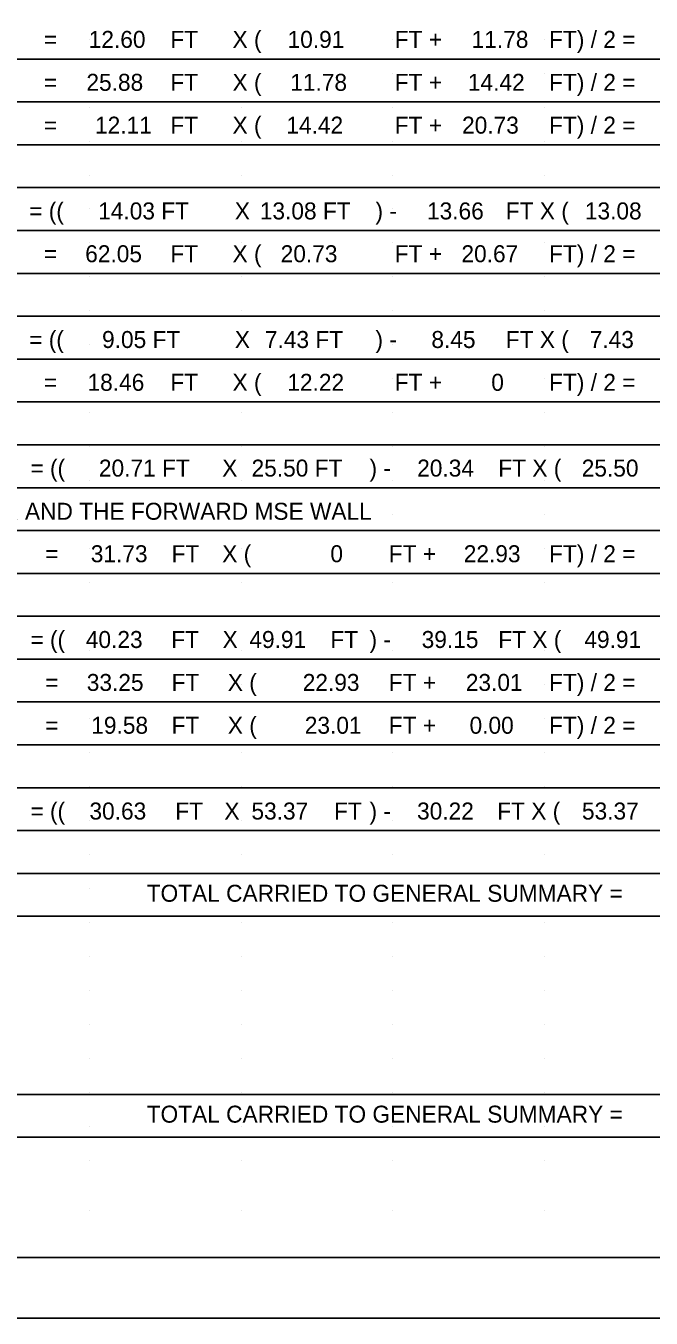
# Model space of a CAD drawing. Extents: x 2073163.5 to 2073197.5, y 634076.4 to 634098.4.
# Drawn here: x 2073186.05 to 2073191.2, y 634076.43 to 634087.09 of the extents above; entities that cross this region are included whole.
import ezdxf

# ---------------------------------------------------------------- set-up
doc = ezdxf.new("R2010")
doc.units = 0
for name, color, linetype in [('SC_Scratch1', 7, 'Continuous'), ('SH_Border', 7, 'Continuous'), ('SH_Cut_Line', 7, 'Continuous'), ('SH_Data', 7, 'Continuous'), ('SH_Text', 7, 'Continuous')]:
    doc.layers.add(name, color=color, linetype=linetype)

msp = doc.modelspace()

# ---------------------------------------------------------------- linework, layer by layer
at = {"layer": 'SC_Scratch1'}
for p, q in [((2073180.369, 634086.814), (2073194.796, 634086.814)), ((2073180.369, 634086.461), (2073194.796, 634086.461)), ((2073180.369, 634086.107), (2073194.796, 634086.107)), ((2073180.369, 634085.754), (2073194.796, 634085.754)), ((2073180.369, 634085.401), (2073194.796, 634085.401)), ((2073180.369, 634085.047), (2073194.796, 634085.047)), ((2073180.369, 634084.694), (2073194.796, 634084.694)), ((2073180.369, 634084.34), (2073194.796, 634084.34)), ((2073180.369, 634083.987), (2073194.796, 634083.987)), ((2073180.369, 634083.634), (2073194.796, 634083.634)), ((2073180.369, 634083.28), (2073194.796, 634083.28)), ((2073180.369, 634082.927), (2073194.796, 634082.927)), ((2073180.369, 634082.574), (2073194.796, 634082.574)), ((2073180.369, 634082.22), (2073194.796, 634082.22)), ((2073180.369, 634081.867), (2073194.796, 634081.867)), ((2073180.369, 634081.514), (2073194.796, 634081.514)), ((2073180.369, 634081.16), (2073194.796, 634081.16)), ((2073180.369, 634080.807), (2073194.796, 634080.807)), ((2073180.369, 634080.454), (2073194.796, 634080.454)), ((2073180.369, 634080.1), (2073194.796, 634080.1)), ((2073180.369, 634079.747), (2073194.796, 634079.747)), ((2073180.369, 634078.279), (2073194.796, 634078.279)), ((2073180.369, 634077.926), (2073194.796, 634077.926))]:
    msp.add_line(p, q, dxfattribs=at)
at = {"layer": 'SH_Border'}
msp.add_lwpolyline([(2073165.007, 634097.934), (2073197.007, 634097.934), (2073197.007, 634076.934), (2073165.007, 634076.934)], close=True, dxfattribs=at)
at = {"layer": 'SH_Cut_Line'}
msp.add_lwpolyline([(2073163.507, 634076.434), (2073197.507, 634076.434), (2073197.507, 634098.434), (2073163.507, 634098.434)], close=True, dxfattribs=at)
at = {"layer": 'SH_Data'}
for p, q in [((2073186.571, 634086.978), (2073186.571, 634086.978)), ((2073187.821, 634086.978), (2073187.821, 634086.978)), ((2073189.071, 634086.978), (2073189.071, 634086.978)), ((2073190.321, 634086.978), (2073190.321, 634086.978)), ((2073186.571, 634086.698), (2073186.571, 634086.698)), ((2073187.821, 634086.698), (2073187.821, 634086.698)), ((2073189.071, 634086.698), (2073189.071, 634086.698)), ((2073190.321, 634086.698), (2073190.321, 634086.698)), ((2073186.571, 634086.418), (2073186.571, 634086.418)), ((2073187.821, 634086.418), (2073187.821, 634086.418)), ((2073189.071, 634086.418), (2073189.071, 634086.418)), ((2073190.321, 634086.418), (2073190.321, 634086.418)), ((2073186.571, 634086.138), (2073186.571, 634086.138)), ((2073187.821, 634086.138), (2073187.821, 634086.138)), ((2073189.071, 634086.138), (2073189.071, 634086.138)), ((2073190.321, 634086.138), (2073190.321, 634086.138)), ((2073186.571, 634085.858), (2073186.571, 634085.858)), ((2073187.821, 634085.858), (2073187.821, 634085.858)), ((2073189.071, 634085.858), (2073189.071, 634085.858)), ((2073190.321, 634085.858), (2073190.321, 634085.858)), ((2073186.571, 634085.578), (2073186.571, 634085.578)), ((2073187.821, 634085.578), (2073187.821, 634085.578)), ((2073189.071, 634085.578), (2073189.071, 634085.578)), ((2073190.321, 634085.578), (2073190.321, 634085.578)), ((2073186.571, 634085.298), (2073186.571, 634085.298)), ((2073187.821, 634085.298), (2073187.821, 634085.298)), ((2073189.071, 634085.298), (2073189.071, 634085.298)), ((2073190.321, 634085.298), (2073190.321, 634085.298)), ((2073186.571, 634085.018), (2073186.571, 634085.018)), ((2073187.821, 634085.018), (2073187.821, 634085.018)), ((2073189.071, 634085.018), (2073189.071, 634085.018)), ((2073190.321, 634085.018), (2073190.321, 634085.018)), ((2073186.571, 634084.738), (2073186.571, 634084.738)), ((2073187.821, 634084.738), (2073187.821, 634084.738)), ((2073189.071, 634084.738), (2073189.071, 634084.738)), ((2073190.321, 634084.738), (2073190.321, 634084.738)), ((2073186.571, 634084.458), (2073186.571, 634084.458)), ((2073187.821, 634084.458), (2073187.821, 634084.458)), ((2073189.071, 634084.458), (2073189.071, 634084.458)), ((2073190.321, 634084.458), (2073190.321, 634084.458)), ((2073186.571, 634084.178), (2073186.571, 634084.178)), ((2073187.821, 634084.178), (2073187.821, 634084.178)), ((2073189.071, 634084.178), (2073189.071, 634084.178)), ((2073190.321, 634084.178), (2073190.321, 634084.178)), ((2073186.571, 634083.898), (2073186.571, 634083.898)), ((2073187.821, 634083.898), (2073187.821, 634083.898)), ((2073189.071, 634083.898), (2073189.071, 634083.898)), ((2073190.321, 634083.898), (2073190.321, 634083.898)), ((2073186.571, 634083.618), (2073186.571, 634083.618)), ((2073187.821, 634083.618), (2073187.821, 634083.618)), ((2073189.071, 634083.618), (2073189.071, 634083.618)), ((2073190.321, 634083.618), (2073190.321, 634083.618)), ((2073186.571, 634083.338), (2073186.571, 634083.338)), ((2073187.821, 634083.338), (2073187.821, 634083.338)), ((2073189.071, 634083.338), (2073189.071, 634083.338)), ((2073190.321, 634083.338), (2073190.321, 634083.338)), ((2073186.571, 634083.058), (2073186.571, 634083.058)), ((2073187.821, 634083.058), (2073187.821, 634083.058)), ((2073189.071, 634083.058), (2073189.071, 634083.058)), ((2073190.321, 634083.058), (2073190.321, 634083.058)), ((2073186.571, 634082.778), (2073186.571, 634082.778)), ((2073187.821, 634082.778), (2073187.821, 634082.778)), ((2073189.071, 634082.778), (2073189.071, 634082.778)), ((2073190.321, 634082.778), (2073190.321, 634082.778)), ((2073186.571, 634082.498), (2073186.571, 634082.498)), ((2073187.821, 634082.498), (2073187.821, 634082.498)), ((2073189.071, 634082.498), (2073189.071, 634082.498)), ((2073190.321, 634082.498), (2073190.321, 634082.498)), ((2073186.571, 634082.218), (2073186.571, 634082.218)), ((2073187.821, 634082.218), (2073187.821, 634082.218)), ((2073189.071, 634082.218), (2073189.071, 634082.218)), ((2073190.321, 634082.218), (2073190.321, 634082.218)), ((2073186.571, 634081.938), (2073186.571, 634081.938)), ((2073187.821, 634081.938), (2073187.821, 634081.938)), ((2073189.071, 634081.938), (2073189.071, 634081.938)), ((2073190.321, 634081.938), (2073190.321, 634081.938)), ((2073186.571, 634081.658), (2073186.571, 634081.658)), ((2073187.821, 634081.658), (2073187.821, 634081.658)), ((2073189.071, 634081.658), (2073189.071, 634081.658)), ((2073190.321, 634081.658), (2073190.321, 634081.658)), ((2073186.571, 634081.378), (2073186.571, 634081.378)), ((2073187.821, 634081.378), (2073187.821, 634081.378)), ((2073189.071, 634081.378), (2073189.071, 634081.378)), ((2073190.321, 634081.378), (2073190.321, 634081.378)), ((2073186.571, 634081.098), (2073186.571, 634081.098)), ((2073187.821, 634081.098), (2073187.821, 634081.098)), ((2073189.071, 634081.098), (2073189.071, 634081.098)), ((2073190.321, 634081.098), (2073190.321, 634081.098)), ((2073186.571, 634080.818), (2073186.571, 634080.818)), ((2073187.821, 634080.818), (2073187.821, 634080.818)), ((2073189.071, 634080.818), (2073189.071, 634080.818)), ((2073190.321, 634080.818), (2073190.321, 634080.818)), ((2073186.571, 634080.538), (2073186.571, 634080.538)), ((2073187.821, 634080.538), (2073187.821, 634080.538)), ((2073189.071, 634080.538), (2073189.071, 634080.538)), ((2073190.321, 634080.538), (2073190.321, 634080.538)), ((2073186.571, 634080.258), (2073186.571, 634080.258)), ((2073187.821, 634080.258), (2073187.821, 634080.258)), ((2073189.071, 634080.258), (2073189.071, 634080.258)), ((2073190.321, 634080.258), (2073190.321, 634080.258)), ((2073186.571, 634079.978), (2073186.571, 634079.978)), ((2073187.821, 634079.978), (2073187.821, 634079.978)), ((2073189.071, 634079.978), (2073189.071, 634079.978)), ((2073190.321, 634079.978), (2073190.321, 634079.978)), ((2073186.571, 634079.698), (2073186.571, 634079.698)), ((2073187.821, 634079.698), (2073187.821, 634079.698)), ((2073189.071, 634079.698), (2073189.071, 634079.698)), ((2073190.321, 634079.698), (2073190.321, 634079.698)), ((2073186.571, 634079.418), (2073186.571, 634079.418)), ((2073187.821, 634079.418), (2073187.821, 634079.418)), ((2073189.071, 634079.418), (2073189.071, 634079.418)), ((2073190.321, 634079.418), (2073190.321, 634079.418)), ((2073186.571, 634079.138), (2073186.571, 634079.138)), ((2073187.821, 634079.138), (2073187.821, 634079.138)), ((2073189.071, 634079.138), (2073189.071, 634079.138)), ((2073190.321, 634079.138), (2073190.321, 634079.138)), ((2073186.571, 634078.858), (2073186.571, 634078.858)), ((2073187.821, 634078.858), (2073187.821, 634078.858)), ((2073189.071, 634078.858), (2073189.071, 634078.858)), ((2073190.321, 634078.858), (2073190.321, 634078.858)), ((2073186.571, 634078.578), (2073186.571, 634078.578)), ((2073187.821, 634078.578), (2073187.821, 634078.578)), ((2073189.071, 634078.578), (2073189.071, 634078.578)), ((2073190.321, 634078.578), (2073190.321, 634078.578)), ((2073186.571, 634078.298), (2073186.571, 634078.298)), ((2073187.821, 634078.298), (2073187.821, 634078.298)), ((2073189.071, 634078.298), (2073189.071, 634078.298)), ((2073190.321, 634078.298), (2073190.321, 634078.298)), ((2073186.571, 634078.018), (2073186.571, 634078.018)), ((2073187.821, 634078.018), (2073187.821, 634078.018)), ((2073189.071, 634078.018), (2073189.071, 634078.018)), ((2073190.321, 634078.018), (2073190.321, 634078.018)), ((2073186.571, 634077.738), (2073186.571, 634077.738)), ((2073187.821, 634077.738), (2073187.821, 634077.738)), ((2073189.071, 634077.738), (2073189.071, 634077.738)), ((2073190.321, 634077.738), (2073190.321, 634077.738)), ((2073186.571, 634077.324), (2073186.571, 634077.324)), ((2073187.821, 634077.324), (2073187.821, 634077.324)), ((2073189.071, 634077.324), (2073189.071, 634077.324)), ((2073190.321, 634077.324), (2073190.321, 634077.324))]:
    msp.add_line(p, q, dxfattribs=at)

# ---------------------------------------------------------------- texts
at = {"layer": 'SH_Text'}
for s, p in [('=', (2073186.196, 634086.906)), ('12.60', (2073186.565, 634086.906)), ('FT', (2073187.238, 634086.906)), ('X (', (2073187.751, 634086.906)), ('10.91', (2073188.205, 634086.906)), ('FT +', (2073189.089, 634086.906)), ('11.78', (2073189.723, 634086.906)), ('FT) / 2 =', (2073190.362, 634086.906)), ('25.88', (2073186.546, 634086.552)), ('FT', (2073187.238, 634086.552)), ('X (', (2073187.751, 634086.552)), ('11.78', (2073188.227, 634086.552)), ('FT +', (2073189.089, 634086.552)), ('14.42', (2073189.692, 634086.552)), ('FT) / 2 =', (2073190.362, 634086.552)), ('=', (2073186.196, 634086.552)), ('=', (2073186.196, 634086.199)), ('12.11', (2073186.617, 634086.199)), ('FT', (2073187.238, 634086.199)), ('X (', (2073187.751, 634086.199)), ('14.42', (2073188.195, 634086.199)), ('FT +', (2073189.089, 634086.199)), ('20.73', (2073189.644, 634086.199)), ('FT) / 2 =', (2073190.362, 634086.199)), ('= ((', (2073186.074, 634085.492)), ('14.03 FT', (2073186.643, 634085.492)), ('X', (2073187.77, 634085.492)), ('13.08 FT', (2073187.976, 634085.492)), (') - ', (2073188.93, 634085.492)), ('13.66', (2073189.355, 634085.492)), ('FT X (', (2073190.005, 634085.492)), ('13.08', (2073190.657, 634085.492)), ('=', (2073186.196, 634085.139)), ('62.05', (2073186.536, 634085.139)), ('FT', (2073187.238, 634085.139)), ('X (', (2073187.751, 634085.139)), ('20.73', (2073188.148, 634085.139)), ('FT +', (2073189.089, 634085.139)), ('20.67', (2073189.639, 634085.139)), ('FT) / 2 =', (2073190.362, 634085.139)), ('= ((', (2073186.074, 634084.432)), ('9.05 FT', (2073186.675, 634084.432)), ('X', (2073187.77, 634084.432)), ('7.43 FT', (2073188.018, 634084.432)), (') - ', (2073188.93, 634084.432)), ('8.45', (2073189.391, 634084.432)), ('FT X (', (2073190.005, 634084.432)), ('7.43', (2073190.697, 634084.432)), ('X (', (2073187.751, 634084.079)), ('FT) / 2 =', (2073190.362, 634084.079)), ('=', (2073186.196, 634084.079)), ('18.46', (2073186.555, 634084.079)), ('FT', (2073187.238, 634084.079)), ('12.22', (2073188.203, 634084.079)), ('FT +', (2073189.089, 634084.079)), ('0', (2073189.885, 634084.079)), ('= ((', (2073186.084, 634083.372)), ('20.71 FT', (2073186.649, 634083.372)), ('X', (2073187.666, 634083.372)), ('25.50 FT', (2073187.908, 634083.372)), (') - ', (2073188.881, 634083.372)), ('20.34', (2073189.274, 634083.372)), ('FT X (', (2073189.943, 634083.372)), ('25.50', (2073190.631, 634083.372)), ('SR 15 - BETWEEN THE WESTBOUND OUTSIDE SHOULDER AND THE FORWARD MSE WALL', (2073180.703, 634083.016)), ('=', (2073186.206, 634082.666)), ('31.73', (2073186.582, 634082.666)), ('FT', (2073187.248, 634082.666)), ('X (', (2073187.666, 634082.666)), ('0', (2073188.558, 634082.666)), ('FT +', (2073189.04, 634082.666)), ('22.93', (2073189.658, 634082.666)), ('FT) / 2 =', (2073190.362, 634082.666)), ('= ((', (2073186.084, 634081.959)), ('40.23', (2073186.541, 634081.959)), ('FT', (2073187.246, 634081.959)), ('X', (2073187.669, 634081.959)), ('49.91', (2073187.89, 634081.959)), ('FT', (2073188.558, 634081.959)), (') - ', (2073188.881, 634081.959)), ('39.15', (2073189.311, 634081.959)), ('FT X (', (2073189.943, 634081.959)), ('49.91', (2073190.653, 634081.959)), ('=', (2073186.206, 634081.605)), ('33.25', (2073186.549, 634081.605)), ('FT', (2073187.248, 634081.605)), ('X (', (2073187.712, 634081.605)), ('22.93', (2073188.33, 634081.605)), ('FT +', (2073189.04, 634081.605)), ('23.01', (2073189.675, 634081.605)), ('FT) / 2 =', (2073190.362, 634081.605)), ('=', (2073186.206, 634081.252)), ('19.58', (2073186.586, 634081.252)), ('FT', (2073187.248, 634081.252)), ('X (', (2073187.712, 634081.252)), ('23.01', (2073188.347, 634081.252)), ('FT +', (2073189.04, 634081.252)), ('0.00', (2073189.706, 634081.252)), ('FT) / 2 =', (2073190.362, 634081.252)), ('= ((', (2073186.084, 634080.545)), ('30.63', (2073186.571, 634080.545)), ('FT', (2073187.279, 634080.545)), ('X', (2073187.684, 634080.545)), ('53.37', (2073187.907, 634080.545)), ('FT', (2073188.589, 634080.545)), (') - ', (2073188.881, 634080.545)), ('30.22', (2073189.273, 634080.545)), ('FT X (', (2073189.934, 634080.545)), ('53.37', (2073190.633, 634080.545)), ('TOTAL CARRIED TO GENERAL SUMMARY =', (2073187.043, 634079.867)), ('TOTAL CARRIED TO GENERAL SUMMARY =', (2073187.043, 634078.046))]:
    msp.add_text(s, height=0.14, rotation=0.0001, dxfattribs=at).set_placement(p)

doc.saveas('drawing.dxf')
